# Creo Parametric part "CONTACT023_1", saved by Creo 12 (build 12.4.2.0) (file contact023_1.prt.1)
Units: Custom; MM, KILOGRAM, SECS

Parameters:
  PTC_WM_ITERATION = "0"
  PTC_WM_VERSION = "-.0"
  PTC_WM_LIFECYCLE_STATE = "In Work"
  PTC_WM_LIFECYCLE = "MO_CADDocument"
  PTC_WM_CREATED_BY = "Maximilian Roepper (Z0017RMS: MO)"
  PTC_WM_CREATED_ON = "18-Sep-26 11:36:42 AM"
  PTC_WM_MODIFIED_BY = "Maximilian Roepper (Z0017RMS: MO)"
  PTC_WM_MODIFIED_ON = "18-Sep-26 11:36:46 AM"
  PDMLINKNUMBER = "PDM000071454959"
  PTC_WM_NAME = "contact023_1.prt"
  PTC_WM_NUMBER = "PDM000071454959"

Other parameters: WEIGHT, WEIGHT_FACTOR, WEIGHT_ADD, _MASS_TEMP, _DIFF_TEMP, MC_ERRORS, SUPPLIER

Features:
  1. coordinate system
  2. datum plane "PRT_YZ"
  3. datum plane "PRT_XY"
  4. datum plane "PRT_XZ"
  5. coordinate system
  6. datum axis
  7. datum axis
  8. datum axis
  9. coordinate system
  10. imported feature

Other named items: PRT, SIEMENS_MO, DRW_VIEW_ORG, PRT_X, PRT_Y, PRT_Z, CS0, ROUGH_GROB

Layers: 00_STD_CSYS-KSYS, 01_STD_PLANES-EBENEN, 02_STD_AXES-ACHSEN, 03_STD_CSYS-KSYS, 24_IMPORT_FEAT-IMPORT_KE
